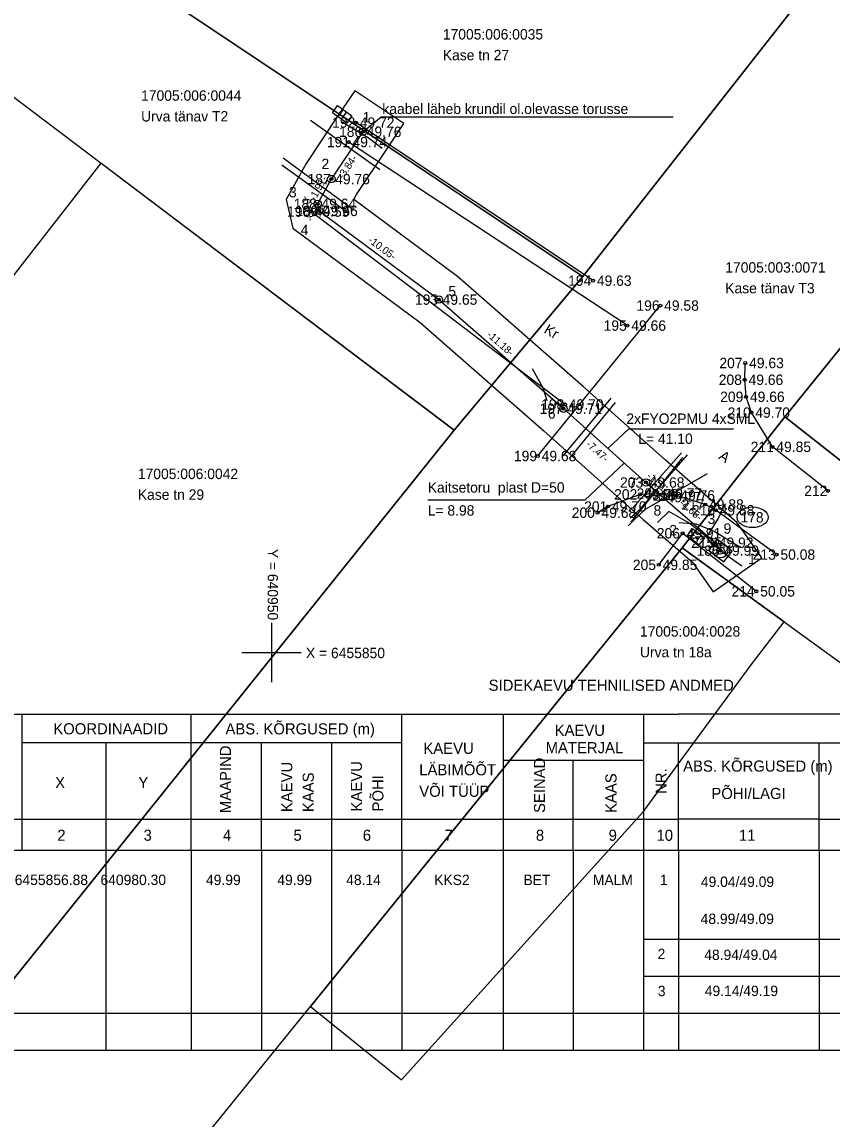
# Model space of a CAD drawing. Extents: x 640876 to 641182, y 6455704 to 6455993.
# Drawn here: x 640933.2 to 640987.8, y 6455818.5 to 6455892.6 of the extents above; entities that cross this region are included whole.
import ezdxf

# ---------------------------------------------------------------- set-up
doc = ezdxf.new("R2010")
doc.units = 0
for name, color, linetype in [('ABIJOONIS', 7, 'Continuous'), ('AED', 7, 'Continuous'), ('JOONSIDE', 7, 'Continuous'), ('KAEVU_NR', 7, 'Continuous'), ('KOORDPUNKT', 7, 'Continuous'), ('KPKAABEL', 7, 'Continuous'), ('KTRASS', 7, 'Continuous'), ('MOOTKORG', 7, 'Continuous'), ('MOOTMPUNKT', 7, 'Continuous'), ('MOOTNR', 7, 'Continuous'), ('MOOTPIIR', 7, 'Continuous'), ('MPKAABEL', 7, 'Continuous'), ('PIIR', 7, 'Continuous'), ('POST', 7, 'Continuous'), ('SIKAEV', 7, 'Continuous'), ('SITRASS', 7, 'Continuous'), ('TEE', 7, 'Continuous'), ('TORU_NR', 7, 'Continuous'), ('VORK', 7, 'Continuous'), ('VTRASS', 7, 'Continuous')]:
    doc.layers.add(name, color=color, linetype=linetype)

msp = doc.modelspace()

# ---------------------------------------------------------------- linework, layer by layer
at = {"layer": 'ABIJOONIS'}
for p, q in [((640926.8, 6455845.849), (640977.481, 6455845.849)), ((640933.155, 6455845.849), (640933.155, 6455836.65)), ((640944.583, 6455836.65), (640944.583, 6455845.849)), ((640958.799, 6455838.741), (640958.799, 6455845.849)), ((640965.634, 6455845.849), (640965.634, 6455836.65)), ((640975.111, 6455845.849), (640975.111, 6455836.65)), ((640997.257, 6455845.849), (640977.481, 6455845.849)), ((640958.799, 6455843.897), (640933.155, 6455843.897)), ((640938.815, 6455843.897), (640938.815, 6455836.65)), ((640949.322, 6455836.65), (640949.322, 6455843.897)), ((640954.06, 6455843.897), (640954.06, 6455836.65)), ((640975.111, 6455843.897), (641007.019, 6455843.897)), ((640977.481, 6455836.65), (640977.481, 6455843.897)), ((640986.958, 6455838.741), (640986.958, 6455843.897)), ((640965.634, 6455842.726), (640975.111, 6455842.726)), ((640970.373, 6455836.65), (640970.373, 6455842.726)), ((640926.8, 6455838.741), (640975.111, 6455838.741)), ((640958.799, 6455836.65), (640958.799, 6455838.741)), ((640975.111, 6455838.741), (640977.481, 6455838.741)), ((640986.958, 6455838.741), (640977.481, 6455838.741)), ((640986.958, 6455838.741), (641007.464, 6455838.741)), ((640986.958, 6455836.65), (640986.958, 6455838.741)), ((640926.8, 6455836.65), (641014.844, 6455836.65)), ((640938.815, 6455836.65), (640938.815, 6455823.15)), ((640938.815, 6455836.65), (640938.815, 6455823.15)), ((640944.583, 6455836.65), (640944.583, 6455823.15)), ((640944.583, 6455836.65), (640944.583, 6455823.15)), ((640949.322, 6455836.65), (640949.322, 6455823.15)), ((640954.06, 6455836.65), (640954.06, 6455823.15)), ((640958.799, 6455836.65), (640958.799, 6455823.15)), ((640965.634, 6455836.65), (640965.634, 6455823.15)), ((640970.373, 6455836.65), (640970.373, 6455823.15)), ((640975.111, 6455836.65), (640975.111, 6455823.15)), ((640977.481, 6455836.65), (640977.481, 6455823.15)), ((640986.958, 6455836.65), (640986.958, 6455823.15)), ((640975.11, 6455830.65), (641014.8, 6455830.65)), ((640975.11, 6455828.15), (641007.019, 6455828.15)), ((640926.8, 6455825.65), (641014.8, 6455825.65)), ((640926.8, 6455825.65), (641014.8, 6455825.65)), ((640926.8, 6455823.15), (641014.8, 6455823.15))]:
    msp.add_line(p, q, dxfattribs=at)
at = {"layer": 'AED'}
msp.add_line((640971.702, 6455875.109), (640955.701, 6455885.783), dxfattribs=at)
msp.add_lwpolyline([(640976.143, 6455855.921), (640977.756, 6455858.052), (640982.729, 6455854.132)], dxfattribs=at)
at = {"layer": 'KAEVU_NR'}
msp.add_ellipse((640982.475, 6455859.13), major_axis=(1.05, 0), ratio=0.666667, dxfattribs=at)
at = {"layer": 'KOORDPUNKT'}
for centre, radius in [((640956.168, 6455885.16), 0.25), ((640956.168, 6455885.16), 0.025), ((640956.168, 6455885.16), 0.0221), ((640956.168, 6455885.16), 0.0191), ((640956.168, 6455885.16), 0.0161), ((640956.168, 6455885.16), 0.0132), ((640956.168, 6455885.16), 0.0102), ((640956.168, 6455885.16), 0.00726), ((640956.168, 6455885.16), 0.0043), ((640954.038, 6455881.966), 0.25), ((640954.038, 6455881.966), 0.025), ((640954.038, 6455881.966), 0.0221), ((640954.038, 6455881.966), 0.0191), ((640954.038, 6455881.966), 0.0161), ((640954.038, 6455881.966), 0.0132), ((640954.038, 6455881.966), 0.0102), ((640954.038, 6455881.966), 0.00726), ((640954.038, 6455881.966), 0.0043), ((640953.111, 6455880.294), 0.25), ((640953.111, 6455880.294), 0.025), ((640953.111, 6455880.294), 0.0221), ((640953.111, 6455880.294), 0.0191), ((640953.111, 6455880.294), 0.0161), ((640953.111, 6455880.294), 0.0132), ((640953.111, 6455880.294), 0.0102), ((640953.111, 6455880.294), 0.00726), ((640953.111, 6455880.294), 0.0043), ((640953.22, 6455879.817), 0.25), ((640953.22, 6455879.817), 0.025), ((640953.22, 6455879.817), 0.0221), ((640953.22, 6455879.817), 0.0191), ((640953.22, 6455879.817), 0.0161), ((640953.22, 6455879.817), 0.0132), ((640953.22, 6455879.817), 0.0102), ((640953.22, 6455879.817), 0.00726), ((640953.22, 6455879.817), 0.0043), ((640961.294, 6455873.83), 0.25), ((640961.294, 6455873.83), 0.025), ((640961.294, 6455873.83), 0.0221), ((640961.294, 6455873.83), 0.0191), ((640961.294, 6455873.83), 0.0161), ((640961.294, 6455873.83), 0.0132), ((640961.294, 6455873.83), 0.0102), ((640961.294, 6455873.83), 0.00726), ((640961.294, 6455873.83), 0.0043), ((640969.709, 6455866.465), 0.25), ((640969.709, 6455866.465), 0.025), ((640969.709, 6455866.465), 0.0221), ((640969.709, 6455866.465), 0.0191), ((640969.709, 6455866.465), 0.0161), ((640969.709, 6455866.465), 0.0132), ((640969.709, 6455866.465), 0.0102), ((640969.709, 6455866.465), 0.00726), ((640969.709, 6455866.465), 0.0043), ((640975.275, 6455861.481), 0.25), ((640975.275, 6455861.481), 0.025), ((640975.275, 6455861.481), 0.0221), ((640975.275, 6455861.481), 0.0191), ((640975.275, 6455861.481), 0.0161), ((640975.275, 6455861.481), 0.0132), ((640975.275, 6455861.481), 0.0102), ((640975.275, 6455861.481), 0.00726), ((640975.275, 6455861.481), 0.0043), ((640976.41, 6455860.49), 0.25), ((640976.41, 6455860.49), 0.025), ((640976.41, 6455860.49), 0.0221), ((640976.41, 6455860.49), 0.0191), ((640976.41, 6455860.49), 0.0161), ((640976.41, 6455860.49), 0.0132), ((640976.41, 6455860.49), 0.0102), ((640976.41, 6455860.49), 0.00726), ((640976.41, 6455860.49), 0.0043), ((640979.915, 6455857.441), 0.25), ((640979.915, 6455857.441), 0.025), ((640979.915, 6455857.441), 0.0221), ((640979.915, 6455857.441), 0.0191), ((640979.915, 6455857.441), 0.0161), ((640979.915, 6455857.441), 0.0132), ((640979.915, 6455857.441), 0.0102), ((640979.915, 6455857.441), 0.00726), ((640979.915, 6455857.441), 0.0043), ((640980.304, 6455856.884), 0.25), ((640980.304, 6455856.884), 0.025), ((640980.304, 6455856.884), 0.0221), ((640980.304, 6455856.884), 0.0191), ((640980.304, 6455856.884), 0.0161), ((640980.304, 6455856.884), 0.0132), ((640980.304, 6455856.884), 0.0102), ((640980.304, 6455856.884), 0.00726), ((640980.304, 6455856.884), 0.0043)]:
    msp.add_circle(centre, radius, dxfattribs=at)
at = {"layer": 'KPKAABEL'}
for p, q in [((640950.793, 6455883.393), (640955.514, 6455879.916)), ((640950.698, 6455882.918), (640955.215, 6455879.667)), ((640974.267, 6455858.804), (640977.764, 6455863.164))]:
    msp.add_line(p, q, dxfattribs=at)
msp.add_lwpolyline([(640968.619, 6455867.004), (640968.332, 6455867.851), (640967.621, 6455869.156)], dxfattribs=at)
at = {"layer": 'KTRASS'}
msp.add_line((640969.711, 6455863.302), (640972.939, 6455867.182), dxfattribs=at)
at = {"layer": 'MOOTMPUNKT'}
for centre in [(640955.701, 6455885.783), (640956.168, 6455885.16), (640955.206, 6455884.464), (640954.038, 6455881.966), (640953.111, 6455880.294), (640952.661, 6455879.772), (640953.22, 6455879.817), (640971.702, 6455875.109), (640961.294, 6455873.83), (640976.244, 6455873.428), (640974.028, 6455872.074), (640981.981, 6455869.547), (640981.941, 6455868.416), (640982.037, 6455867.267), (640969.709, 6455866.465), (640969.81, 6455866.748), (640982.397, 6455866.199), (640967.975, 6455863.269), (640983.817, 6455863.886), (640975.275, 6455861.481), (640974.878, 6455860.68), (640976.467, 6455860.734), (640977.331, 6455860.605), (640987.568, 6455860.915), (640972.714, 6455859.86), (640979.277, 6455859.995), (640979.994, 6455859.606), (640972.015, 6455859.44), (640977.756, 6455858.052), (640979.934, 6455857.414), (640980.304, 6455856.884), (640984.093, 6455856.615), (640976.143, 6455855.921), (640982.729, 6455854.132)]:
    msp.add_circle(centre, 0.1, dxfattribs=at)
at = {"layer": 'MOOTPIIR'}
msp.add_lwpolyline([(640955.614, 6455887.934), (640954.504, 6455886.27), (640952.329, 6455883.007), (640950.991, 6455880.594), (640951.435, 6455878.651), (640960.038, 6455872.272), (640968.383, 6455864.967), (640973.95, 6455859.983), (640975.096, 6455858.982), (640978.416, 6455856.093), (640978.665, 6455855.738), (640979.81, 6455854.099), (640983.089, 6455856.39), (640981.943, 6455858.03), (640981.413, 6455858.788), (640977.724, 6455861.998), (640976.6, 6455862.979), (640971.035, 6455867.963), (640962.55, 6455875.388), (640955.554, 6455880.576), (640955.747, 6455880.925), (640957.832, 6455884.05), (640958.942, 6455885.714)], close=True, dxfattribs=at)
at = {"layer": 'MPKAABEL'}
msp.add_line((640974.384, 6455859.775), (640977.685, 6455863.488), dxfattribs=at)
for points in [[(640954.771, 6455885.82), (640956.533, 6455884.776), (640957.481, 6455884.05)], [(640974.22, 6455859.082), (640974.89, 6455859.69), (640978.087, 6455863.351)], [(640974.068, 6455858.565), (640975.193, 6455859.664), (640979.429, 6455862.077)]]:
    msp.add_lwpolyline(points, dxfattribs=at)
at = {"layer": 'PIIR'}
for points in [[(640960.73, 6455969.25), (640920.16, 6455909.31), (640971.01, 6455875.38), (640993.57, 6455904.12), (640970.23, 6455922.96), (640989.11, 6455946.27)], [(640971.01, 6455875.38), (640920.16, 6455909.31), (640889.02, 6455933.34), (640882.97, 6455925.5), (640914.68, 6455901.06), (640938.5, 6455883.04), (640962.33, 6455865.02)], [(640984.64, 6455865.92), (641012.04, 6455844.39), (641032.25, 6455870.2), (641005.01, 6455891.09)], [(640962.33, 6455865.02), (640938.49, 6455883.03), (640906.91, 6455842.53), (640929.52, 6455824.17)], [(640984.64, 6455865.92), (640977.72, 6455857.07), (640984.6, 6455852.08), (640995.15, 6455844.43), (641032.96, 6455815.89), (641051.96, 6455801.51), (641058.78, 6455795.87), (641097.79, 6455765.96), (641114.38, 6455753.24), (641130.25, 6455741.07), (641146.12, 6455728.91), (641143.13, 6455725.04), (641170.91, 6455704.35), (641182.28, 6455716.38), (641177.47, 6455716.39), (641127.83, 6455755.09), (641099.43, 6455777.27), (641081.98, 6455790.7), (641064.46, 6455804.29), (641046.64, 6455817.21), (641029.34, 6455830.8), (641012.04, 6455844.39)], [(640952.64, 6455826.1), (640958.77, 6455821.15), (640975.1, 6455839.27), (640977.64, 6455842.72), (640982.37, 6455849.18), (640984.6, 6455852.08), (640977.72, 6455857.07)]]:
    msp.add_lwpolyline(points, close=True, dxfattribs=at)
msp.add_lwpolyline([(641037.5, 6455958.58), (641024.93, 6455943.02), (641012.36, 6455927.46), (640993.57, 6455904.12), (640971.01, 6455875.38), (640962.33, 6455865.02), (640876.41, 6455757.97), (640888.17, 6455749.25), (640894.56, 6455746.37), (640902.45, 6455758.84), (640915.55, 6455775.13), (640928.34, 6455790.92), (640960.9, 6455766.7), (640964.64, 6455771.22), (640941.6, 6455788.51), (640929.99, 6455798.13), (640933.13, 6455802.02), (640952.64, 6455826.1), (640977.72, 6455857.07), (640984.64, 6455865.92), (641005.01, 6455891.09), (641032.25, 6455870.2), (641049.71, 6455856.81)], dxfattribs=at)
at = {"layer": 'POST'}
for p, q in [((640954.833, 6455886.66), (640954.485, 6455886.175)), ((640955.053, 6455886.501), (640954.705, 6455886.016))]:
    msp.add_line(p, q, dxfattribs=at)
for points in [[(640954.458, 6455886.929), (640955.428, 6455886.232), (640955.08, 6455885.747), (640954.11, 6455886.444)], [(640978.436, 6455858.35), (640979.224, 6455857.735), (640978.855, 6455857.262), (640978.067, 6455857.877)]]:
    msp.add_lwpolyline(points, close=True, dxfattribs=at)
for centre, radius in [((640978.488, 6455857.929), 0.0304), ((640978.488, 6455857.929), 0.029), ((640978.488, 6455857.929), 0.0277), ((640978.488, 6455857.929), 0.0263), ((640978.488, 6455857.929), 0.0249), ((640978.488, 6455857.929), 0.0236), ((640978.488, 6455857.929), 0.0222), ((640978.488, 6455857.929), 0.0209), ((640978.488, 6455857.929), 0.0195), ((640978.488, 6455857.929), 0.0181), ((640978.488, 6455857.929), 0.0168), ((640978.488, 6455857.929), 0.0154), ((640978.488, 6455857.929), 0.014), ((640978.488, 6455857.929), 0.0127), ((640978.488, 6455857.929), 0.0113), ((640978.488, 6455857.929), 0.00996), ((640978.488, 6455857.929), 0.0086), ((640978.488, 6455857.929), 0.00724), ((640978.488, 6455857.929), 0.00587), ((640978.488, 6455857.929), 0.00451), ((640978.488, 6455857.929), 0.00315), ((640978.488, 6455857.929), 0.00179), ((640978.488, 6455857.929), 0.000426), ((640978.803, 6455857.683), 0.0304), ((640978.803, 6455857.683), 0.029), ((640978.803, 6455857.683), 0.0277), ((640978.803, 6455857.683), 0.0263), ((640978.803, 6455857.683), 0.0249), ((640978.803, 6455857.683), 0.0236), ((640978.803, 6455857.683), 0.0222), ((640978.803, 6455857.683), 0.0209), ((640978.803, 6455857.683), 0.0195), ((640978.803, 6455857.683), 0.0181), ((640978.803, 6455857.683), 0.0168), ((640978.803, 6455857.683), 0.0154), ((640978.803, 6455857.683), 0.014), ((640978.803, 6455857.683), 0.0127), ((640978.803, 6455857.683), 0.0113), ((640978.803, 6455857.683), 0.00996), ((640978.803, 6455857.683), 0.0086), ((640978.803, 6455857.683), 0.00724), ((640978.803, 6455857.683), 0.00587), ((640978.803, 6455857.683), 0.00451), ((640978.803, 6455857.683), 0.00315), ((640978.803, 6455857.683), 0.00179), ((640978.803, 6455857.683), 0.000426)]:
    msp.add_circle(centre, radius, dxfattribs=at)
at = {"layer": 'SIKAEV'}
for p, q in [((640980.304, 6455857.384), (640980.304, 6455856.884)), ((640980.304, 6455856.884), (640979.889, 6455856.609)), ((640980.304, 6455856.884), (640980.719, 6455856.609))]:
    msp.add_line(p, q, dxfattribs=at)
msp.add_lwpolyline([(640979.506, 6455856.92), (640980.528, 6455856.117), (640981.102, 6455856.848), (640980.08, 6455857.651)], close=True, dxfattribs=at)
msp.add_circle((640980.304, 6455856.884), 0.5, dxfattribs=at)
at = {"layer": 'SITRASS'}
msp.add_line((640957.313, 6455882.59), (640952.63, 6455885.91), dxfattribs=at)
for points in [[(640956.168, 6455885.16), (640957.412, 6455886.159), (640977.122, 6455886.159)], [(640956.168, 6455885.16), (640954.038, 6455881.966), (640953.111, 6455880.294), (640953.22, 6455879.817), (640961.294, 6455873.83), (640969.709, 6455866.465), (640975.275, 6455861.481), (640976.41, 6455860.49), (640979.915, 6455857.441), (640980.304, 6455856.884)], [(640976.41, 6455860.49), (640975.275, 6455861.481), (640969.709, 6455866.465)], [(640972.713, 6455863.775), (640974.113, 6455865.095), (640981.185, 6455865.095)], [(640973.812, 6455862.791), (640971.15, 6455860.295), (640960.546, 6455860.295)], [(640979.394, 6455857.788), (640980.145, 6455859.022), (640980.647, 6455860.062)], [(640979.394, 6455857.788), (640978.248, 6455858.719), (640976.82, 6455859.525), (640976.057, 6455858.786)], [(640977.5, 6455858.79), (640978.672, 6455858.691), (640979.928, 6455858.162), (640981.64, 6455857.111)], [(640980.304, 6455856.884), (640979.793, 6455857.286), (640979.394, 6455857.788), (640978.646, 6455857.806)], [(640980.304, 6455856.884), (640980.831, 6455856.503), (640981.749, 6455855.847)]]:
    msp.add_lwpolyline(points, dxfattribs=at)
at = {"layer": 'TEE'}
for points in [[(640974.028, 6455872.074), (640955.206, 6455884.464)], [(640969.81, 6455866.748), (640952.661, 6455879.772)], [(640967.975, 6455863.269), (640976.244, 6455873.428)], [(640987.568, 6455860.915), (640983.817, 6455863.886), (640982.397, 6455866.199), (640982.037, 6455867.267), (640981.941, 6455868.416), (640981.981, 6455869.547)], [(640984.093, 6455856.615), (640979.994, 6455859.606), (640979.277, 6455859.995), (640977.331, 6455860.605), (640976.467, 6455860.734), (640974.878, 6455860.68), (640972.714, 6455859.86), (640972.015, 6455859.44)]]:
    msp.add_lwpolyline(points, dxfattribs=at)
at = {"layer": 'VORK'}
for p, q in [((640950, 6455852), (640950, 6455848)), ((640948, 6455850), (640952, 6455850))]:
    msp.add_line(p, q, dxfattribs=at)
at = {"layer": 'VTRASS'}
msp.add_line((640970.108, 6455863.099), (640973.212, 6455866.886), dxfattribs=at)

# ---------------------------------------------------------------- texts
at = {"layer": 'ABIJOONIS'}
for s, height, p in [('SIDEKAEVU TEHNILISED ANDMED', 0.75, (640964.657, 6455847.416)), ('KOORDINAADID', 0.75, (640935.27, 6455844.476)), ('ABS. KÕRGUSED (m)', 0.75, (640946.893, 6455844.471)), ('KAEVU', 0.75, (640969.113, 6455844.37)), ('MATERJAL', 0.75, (640968.503, 6455843.2)), ('ABS. KÕRGUSED (m)', 0.75, (640977.787, 6455841.959)), ('X', 0.75, (640935.396, 6455840.842)), ('Y', 0.75, (640941.014, 6455840.853)), ('PÕHI/LAGI', 0.75, (640979.692, 6455840.11)), ('2', 0.75, (640935.542, 6455837.29)), ('3', 0.75, (640941.366, 6455837.29)), ('4', 0.75, (640946.724, 6455837.29)), ('5', 0.75, (640951.484, 6455837.29)), ('6', 0.75, (640956.165, 6455837.29)), ('7', 0.75, (640961.672, 6455837.29)), ('8', 0.75, (640967.845, 6455837.29)), ('9', 0.75, (640972.757, 6455837.29)), ('10', 0.75, (640975.989, 6455837.29)), ('11', 0.75, (640981.553, 6455837.29)), ('6455856.88', 0.7, (640932.669, 6455834.3)), ('640980.30', 0.7, (640938.455, 6455834.3)), ('49.99', 0.7, (640945.578, 6455834.3)), ('49.99', 0.7, (640950.393, 6455834.3)), ('48.14', 0.7, (640955.041, 6455834.3)), ('KKS2', 0.7, (640960.983, 6455834.3)), ('BET', 0.7, (640967.004, 6455834.3)), ('MALM', 0.7, (640971.691, 6455834.3)), ('1', 0.7, (640976.223, 6455834.3)), ('49.04/49.09', 0.7, (640978.982, 6455834.172)), ('48.99/49.09', 0.7, (640978.968, 6455831.672)), ('2', 0.7, (640976.062, 6455829.3)), ('48.94/49.04', 0.7, (640979.211, 6455829.24)), ('3', 0.7, (640976.076, 6455826.8)), ('49.14/49.19', 0.7, (640979.247, 6455826.806))]:
    msp.add_text(s, height=height, dxfattribs=at).set_placement(p)
for s, rotation, p in [('MAAPIND', 90, (640947.267, 6455839.155)), (' KAEVU', 0.02438, (640959.972, 6455843.157)), ('KAEVU', 90, (640951.404, 6455839.226)), ('KAEVU', 90, (640956.106, 6455839.27)), ('LÄBIMÕÕT', 0.02438, (640959.973, 6455841.707)), ('SEINAD', 90, (640968.465, 6455839.167)), ('KAAS', 90, (640952.854, 6455839.226)), ('KAAS', 90, (640973.292, 6455839.167)), ('NR.', 90, (640976.672, 6455840.456)), ('PÕHI', 90, (640957.556, 6455839.27)), ('VÕI TÜÜP', 0.02438, (640959.973, 6455840.257))]:
    msp.add_text(s, height=0.75, rotation=rotation, dxfattribs=at).set_placement(p)
at = {"layer": 'JOONSIDE'}
for s, rotation, p in [('-3.84-', 56.30165, (640954.844, 6455881.93)), ('-1.91-', 60.99488, (640952.938, 6455880.469)), ('-0.49-', 282.87174, (640952.054, 6455880.786)), ('-10.05-', 323.44247, (640956.477, 6455877.744)), ('-11.18-', 318.80685, (640964.493, 6455871.39)), ('-7.47-', 318.15757, (640971.189, 6455863.994)), ('-1.51-', 318.88118, (640975.27, 6455861.85)), ('-4.65-', 318.97515, (640977.492, 6455860.022))]:
    msp.add_text(s, height=0.5, rotation=rotation, dxfattribs=at).set_placement(p)
at = {"layer": 'KAEVU_NR'}
msp.add_text('178', height=0.7, dxfattribs=at).set_placement((640981.656, 6455858.78))
at = {"layer": 'KOORDPUNKT'}
for s, p in [('1 ', (640956.146, 6455885.794)), ('2 ', (640953.374, 6455882.641)), ('3 ', (640951.182, 6455880.729)), ('4 ', (640951.967, 6455878.18)), ('5 ', (640961.939, 6455874.047)), ('6 ', (640968.652, 6455865.788)), ('7 ', (640974.109, 6455861.087)), ('8 ', (640975.79, 6455859.245)), ('9 ', (640980.515, 6455858.023))]:
    msp.add_text(s, height=0.7, dxfattribs=at).set_placement(p)
at = {"layer": 'MOOTKORG'}
for s, p in [(' 49.72', (640955.701, 6455885.433)), (' 49.76', (640956.168, 6455884.81)), (' 49.74', (640955.206, 6455884.114)), (' 49.76', (640954.038, 6455881.616)), (' 49.64', (640953.111, 6455879.944)), (' 49.59', (640952.661, 6455879.422)), (' 49.66', (640953.22, 6455879.467)), (' 49.63', (640971.702, 6455874.759)), (' 49.65', (640961.294, 6455873.48)), (' 49.58', (640976.244, 6455873.078)), (' 49.66', (640974.028, 6455871.724)), (' 49.63', (640981.981, 6455869.197)), (' 49.66', (640981.941, 6455868.066)), (' 49.70', (640969.81, 6455866.398)), (' 49.66', (640982.037, 6455866.917)), (' 49.71', (640969.709, 6455866.115)), (' 49.70', (640982.397, 6455865.849)), (' 49.85', (640983.817, 6455863.536)), (' 49.68', (640967.975, 6455862.919)), (' 49.68', (640975.275, 6455861.131)), (' 49.70', (640974.878, 6455860.33)), (' 49.77', (640976.467, 6455860.384)), (' 49.77', (640976.41, 6455860.14)), (' 49.76', (640977.331, 6455860.255)), (' 49.88', (640979.277, 6455859.645)), (' 49.68', (640972.015, 6455859.09)), (' 49.70', (640972.714, 6455859.51)), (' 49.88', (640979.994, 6455859.256)), (' 49.91', (640977.756, 6455857.702)), (' 49.92', (640979.934, 6455857.064)), (' 49.99', (640980.304, 6455856.534)), (' 50.08', (640984.093, 6455856.265)), (' 49.85', (640976.143, 6455855.571)), (' 50.05', (640982.729, 6455853.782))]:
    msp.add_text(s, height=0.7, dxfattribs=at).set_placement(p)
at = {"layer": 'MOOTNR'}
for s, p in [('192 ', (640954.091, 6455885.433)), ('186 ', (640954.558, 6455884.81)), ('191 ', (640953.736, 6455884.114)), ('187 ', (640952.428, 6455881.616)), ('188 ', (640951.501, 6455879.944)), ('190 ', (640951.051, 6455879.422)), ('189 ', (640951.61, 6455879.467)), ('194 ', (640970.022, 6455874.759)), ('193 ', (640959.684, 6455873.48)), ('196 ', (640974.634, 6455873.078)), ('195 ', (640972.418, 6455871.724)), ('207 ', (640980.231, 6455869.197)), ('208 ', (640980.191, 6455868.066)), ('198 ', (640968.2, 6455866.398)), ('209 ', (640980.287, 6455866.917)), ('197 ', (640968.099, 6455866.115)), ('210 ', (640980.787, 6455865.849)), ('211 ', (640982.347, 6455863.536)), ('199 ', (640966.365, 6455862.919)), ('203 ', (640973.525, 6455861.131)), ('202 ', (640973.128, 6455860.33)), ('204 ', (640974.647, 6455860.384)), ('212 ', (640985.958, 6455860.565)), ('218 ', (640975.721, 6455860.255)), ('217 ', (640977.667, 6455859.645)), ('200 ', (640970.265, 6455859.09)), ('201 ', (640971.104, 6455859.51)), ('216 ', (640978.384, 6455859.256)), ('206 ', (640976.006, 6455857.702)), ('215 ', (640978.324, 6455857.064)), ('185 ', (640978.694, 6455856.534)), ('213 ', (640982.483, 6455856.265)), ('205 ', (640974.393, 6455855.571)), ('214 ', (640981.049, 6455853.782))]:
    msp.add_text(s, height=0.7, dxfattribs=at).set_placement(p)
at = {"layer": 'PIIR'}
for s, p in [('17005:006:0035', (640961.565, 6455891.388)), ('Kase tn 27', (640961.565, 6455889.988)), ('17005:006:0044', (640941.198, 6455887.255)), ('Urva tänav T2', (640941.198, 6455885.855)), ('17005:003:0071', (640980.63, 6455875.65)), ('Kase tänav T3', (640980.63, 6455874.25)), ('17005:006:0042', (640940.979, 6455861.711)), ('Kase tn 29', (640940.979, 6455860.311)), ('17005:004:0028', (640974.872, 6455851.075)), ('Urva tn 18a', (640974.872, 6455849.675))]:
    msp.add_text(s, height=0.7, dxfattribs=at).set_placement(p)
at = {"layer": 'SITRASS'}
for s, p in [('kaabel läheb krundil ol.olevasse torusse', (640957.482, 6455886.357)), ('2xFYO2PMU 4xSML', (640973.953, 6455865.439)), ('L= 41.10', (640974.763, 6455864.085)), ('Kaitsetoru  plast D=50', (640960.546, 6455860.795)), ('L= 8.98', (640960.546, 6455859.245))]:
    msp.add_text(s, height=0.7, dxfattribs=at).set_placement(p)
at = {"layer": 'TEE'}
for s, rotation, p in [('Kr', 329.10424, (640968.333, 6455871.614)), ('A', 325.04485, (640980.129, 6455863.119))]:
    msp.add_text(s, height=0.7, rotation=rotation, dxfattribs=at).set_placement(p)
at = {"layer": 'TORU_NR'}
for s, p in [('3', (640979.437, 6455858.68)), ('2', (640976.854, 6455857.913)), ('1', (640982.169, 6455855.976))]:
    msp.add_text(s, height=0.7, dxfattribs=at).set_placement(p)
at = {"layer": 'VORK'}
msp.add_text('Y = 640950 ', height=0.7, rotation=270, dxfattribs=at).set_placement((640949.739, 6455856.998))
msp.add_text('X = 6455850', height=0.7, dxfattribs=at).set_placement((640952.326, 6455849.619))

doc.saveas('drawing.dxf')
